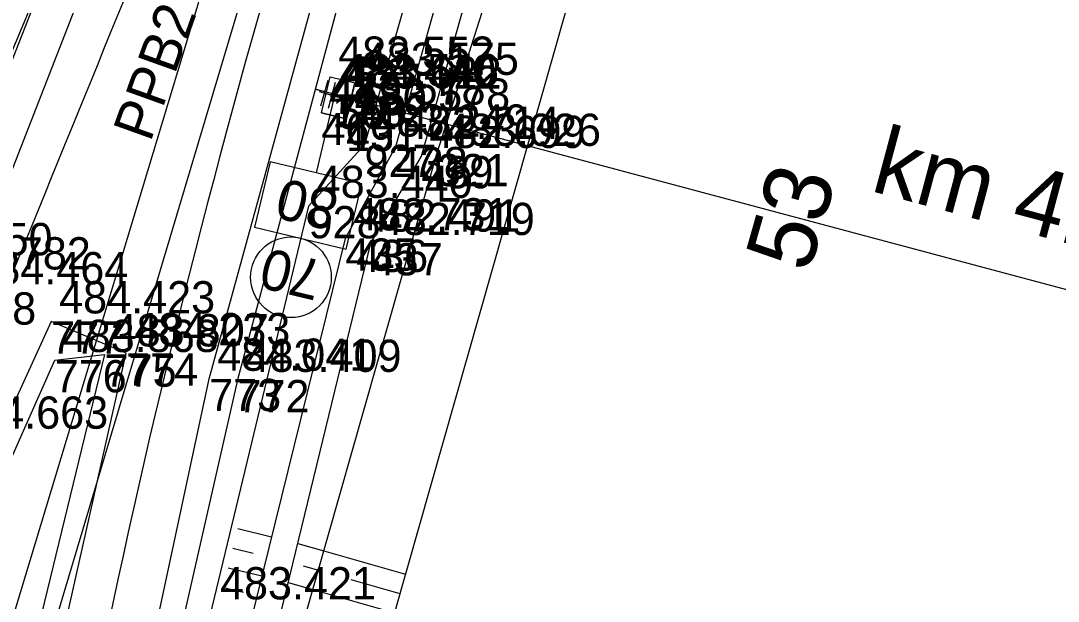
# Model space of a CAD drawing. Extents: x -874038 to -859694, y -1059487 to -1049069.
# Drawn here: x -866876 to -866837.42, y -1050772.45 to -1050750.85 of the extents above; entities that cross this region are included whole.
import ezdxf

# ---------------------------------------------------------------- set-up
doc = ezdxf.new("R2010")
doc.units = 0
for name, color, linetype in [('Vrstva 1', 7, 'Continuous'), ('Vrstva 11', 7, 'Continuous'), ('Vrstva 12', 7, 'Continuous'), ('Vrstva 13', 7, 'Continuous'), ('Vrstva 23', 7, 'Continuous'), ('Vrstva 3', 7, 'Continuous'), ('Vrstva 4', 7, 'Continuous'), ('Vrstva 44', 7, 'Continuous'), ('Vrstva 48', 7, 'Continuous'), ('Vrstva 49', 7, 'Continuous'), ('Vrstva 5', 7, 'Continuous'), ('Vrstva 6', 7, 'Continuous'), ('Vrstva 60', 7, 'Continuous'), ('Vrstva 61', 7, 'Continuous'), ('Vrstva 63', 7, 'Continuous'), ('Vrstva 7', 7, 'Continuous')]:
    doc.layers.add(name, color=color, linetype=linetype)

msp = doc.modelspace()

# ---------------------------------------------------------------- linework, layer by layer
at = {"layer": 'Vrstva 1'}
msp.add_arc((-866539.48, -1050843.456), 340.562, 163.73547, 173.43306, dxfattribs=at)
msp.add_spline([(-866866.581, -1050736.738), (-866870.906, -1050747.039), (-866878.845, -1050766.33), (-866887.686, -1050786.453)], degree=3, dxfattribs=at)
at = {"layer": 'Vrstva 11'}
for p, q in [((-866864.834, -1050754.023), (-866864.561, -1050753.06)), ((-866864.697, -1050753.542), (-866863.735, -1050753.814)), ((-866863.871, -1050754.296), (-866863.598, -1050753.333))]:
    msp.add_line(p, q, dxfattribs=at)
at = {"layer": 'Vrstva 12'}
for points in [[(-866864.816, -1050754.28), (-866864.492, -1050752.94), (-866863.577, -1050753.167), (-866863.9, -1050754.502), (-866864.816, -1050754.28)], [(-866864.492, -1050752.94), (-866863.577, -1050753.167)], [(-866863.9, -1050754.502), (-866863.9, -1050754.502), (-866863.577, -1050753.167), (-866863.577, -1050753.167)], [(-866864.816, -1050754.28), (-866863.9, -1050754.502)]]:
    msp.add_lwpolyline(points, dxfattribs=at)
at = {"layer": 'Vrstva 13'}
for p, q in [((-866859.113, -1050745.02), (-866862.056, -1050755.548)), ((-866862.056, -1050755.548), (-866863.928, -1050758.953)), ((-866863.928, -1050758.953), (-866870.485, -1050785.449))]:
    msp.add_line(p, q, dxfattribs=at)
msp.add_lwpolyline([(-866869.435, -1050785.682), (-866862.985, -1050759.125), (-866861.101, -1050755.887), (-866858.093, -1050745.283), (-866857.657, -1050739.624), (-866853.141, -1050726.153)], dxfattribs=at)
at = {"layer": 'Vrstva 23'}
msp.add_lwpolyline([(-866860.091, -1050744.519), (-866863.217, -1050755.466), (-866865.293, -1050757.745), (-866868.888, -1050772.679), (-866871.977, -1050788.759), (-866873.748, -1050800.936), (-866875.048, -1050813.205), (-866876.041, -1050829.553), (-866876.177, -1050845.923), (-866875.472, -1050862.297), (-866873.902, -1050878.655), (-866871.491, -1050894.865), (-866868.278, -1050910.955), (-866864.193, -1050926.852), (-866859.318, -1050942.487)], dxfattribs=at)
at = {"layer": 'Vrstva 4'}
for p, q in [((-866868.991, -1050764.175), (-866863.095, -1050742.706)), ((-866862.275, -1050743.026), (-866867.938, -1050764.216)), ((-866874.869, -1050762.04), (-866892.274, -1050800.212)), ((-866872.076, -1050763.224), (-866874.869, -1050762.04)), ((-866872.878, -1050763.268), (-866876.724, -1050779.104)), ((-866875.741, -1050779.509), (-866872.076, -1050763.224)), ((-866874.734, -1050763.477), (-866872.878, -1050763.268)), ((-866891.238, -1050800.767), (-866874.734, -1050763.477)), ((-866872.377, -1050779.959), (-866868.991, -1050764.175)), ((-866867.938, -1050764.216), (-866871.451, -1050779.65))]:
    msp.add_line(p, q, dxfattribs=at)
for points in [[(-866878.099, -1050760.956), (-866869.769, -1050739.599), (-866865.751, -1050728.95), (-866863.436, -1050724.369)], [(-866892.733, -1050790.985), (-866891.263, -1050788.067), (-866879.491, -1050760.405), (-866874.327, -1050747.254)]]:
    msp.add_lwpolyline(points, dxfattribs=at)
at = {"layer": 'Vrstva 44'}
for points in [[(-866912.752, -1050826.723), (-866890.904, -1050786.8), (-866874.15, -1050746.784), (-866858.678, -1050710.211), (-866845.122, -1050668.894)], [(-866881.51, -1050790.314), (-866868.997, -1050748.913), (-866874.15, -1050746.784)]]:
    msp.add_lwpolyline(points, dxfattribs=at)
at = {"layer": 'Vrstva 48'}
for p, q in [((-866866.676, -1050770.059), (-866867.928, -1050769.758)), ((-866867.355, -1050770.668), (-866868.104, -1050770.487)), ((-866865.698, -1050770.295), (-866864.726, -1050770.572)), ((-866864.726, -1050770.572), (-866861.691, -1050771.435)), ((-866867.037, -1050771.516), (-866868.279, -1050771.216)), ((-866865.497, -1050771.132), (-866864.931, -1050771.293)), ((-866866.052, -1050771.753), (-866865.136, -1050772.014)), ((-866863.717, -1050771.638), (-866861.896, -1050772.156)), ((-866867.712, -1050772.124), (-866868.455, -1050771.946)), ((-866865.136, -1050772.015), (-866862.101, -1050772.877))]:
    msp.add_line(p, q, dxfattribs=at)
at = {"layer": 'Vrstva 49'}
for points in [[(-866870.679, -1050875.747), (-866872.53, -1050852.558), (-866873.22, -1050828.055), (-866867.257, -1050779.466), (-866860.524, -1050755.809), (-866853.019, -1050732.306), (-866844.747, -1050709.076), (-866836.666, -1050685.758), (-866827.324, -1050663.004), (-866815.747, -1050641.544), (-866813.39, -1050638.57)], [(-866813.39, -1050638.57), (-866814.614, -1050641.108), (-866825.174, -1050662.382), (-866840.16, -1050699.594), (-866853.045, -1050741.012), (-866865.294, -1050784.112), (-866869.459, -1050806.077), (-866871.336, -1050827.203), (-866872.249, -1050850.439), (-866870.679, -1050875.747)]]:
    msp.add_lwpolyline(points, dxfattribs=at)
at = {"layer": 'Vrstva 5'}
msp.add_line((-866863.585, -1050753.766), (-866865.043, -1050753.414), dxfattribs=at)
msp.add_lwpolyline([(-866864.314, -1050753.59), (-866865.016, -1050756.507), (-866866.717, -1050756.097), (-866867.302, -1050758.528), (-866863.9, -1050759.347), (-866863.315, -1050756.916), (-866865.016, -1050756.507)], dxfattribs=at)
msp.add_circle((-866865.952, -1050760.396), 1.5, dxfattribs=at)
at = {"layer": 'Vrstva 6'}
msp.add_line((-866824.051, -1050764.35), (-866865.046, -1050753.394), dxfattribs=at)
at = {"layer": 'Vrstva 60'}
for p, q in [((-866864.492, -1050752.94), (-866864.492, -1050752.94)), ((-866863.577, -1050753.167), (-866863.577, -1050753.167)), ((-866863.577, -1050753.167), (-866863.577, -1050753.167)), ((-866864.421, -1050753.622), (-866864.421, -1050753.622)), ((-866864.314, -1050753.59), (-866864.314, -1050753.59)), ((-866864.216, -1050753.678), (-866864.216, -1050753.678)), ((-866864.816, -1050754.28), (-866864.816, -1050754.28)), ((-866863.9, -1050754.502), (-866863.9, -1050754.502)), ((-866863.9, -1050754.502), (-866863.9, -1050754.502)), ((-866863.217, -1050755.466), (-866863.217, -1050755.466)), ((-866862.056, -1050755.548), (-866862.056, -1050755.548)), ((-866861.101, -1050755.887), (-866861.101, -1050755.887)), ((-866860.524, -1050755.809), (-866860.524, -1050755.809)), ((-866865.293, -1050757.745), (-866865.293, -1050757.745)), ((-866863.928, -1050758.953), (-866863.928, -1050758.953)), ((-866863.526, -1050759), (-866863.526, -1050759)), ((-866862.985, -1050759.125), (-866862.985, -1050759.125)), ((-866874.869, -1050762.04), (-866874.869, -1050762.04)), ((-866872.878, -1050763.268), (-866872.878, -1050763.268)), ((-866872.076, -1050763.224), (-866872.076, -1050763.224)), ((-866874.734, -1050763.477), (-866874.734, -1050763.477)), ((-866868.991, -1050764.175), (-866868.991, -1050764.175)), ((-866867.938, -1050764.216), (-866867.938, -1050764.216))]:
    msp.add_line(p, q, dxfattribs=at)
at = {"layer": 'Vrstva 63'}
msp.add_line((-866878.429, -1050785.654), (-866847.948, -1050683.577), dxfattribs=at)
at = {"layer": 'Vrstva 7'}
for p, q in [((-866864.553, -1050754.104), (-866864.289, -1050753.14)), ((-866864.903, -1050753.49), (-866863.939, -1050753.754))]:
    msp.add_line(p, q, dxfattribs=at)

# ---------------------------------------------------------------- texts
at = {"layer": 'Vrstva 11'}
msp.add_text('53', height=2.5, rotation=74.1581, dxfattribs=at).set_placement((-866846.68, -1050760.278))
at = {"layer": 'Vrstva 3'}
msp.add_text('PPB2', height=1.5, rotation=70.2618, dxfattribs=at).set_placement((-866871.176, -1050755.399))
at = {"layer": 'Vrstva 5'}
for s, p in [('80', (-866864.092, -1050757.221)), ('70', (-866864.684, -1050759.815))]:
    msp.add_text(s, height=1.5, rotation=166.4665, dxfattribs=at).set_placement(p)
at = {"layer": 'Vrstva 6'}
msp.add_text('km 411,776', height=2.5, rotation=345.0373, dxfattribs=at).set_placement((-866844.455, -1050757.171))
at = {"layer": 'Vrstva 60'}
for s, p in [('47', (-866864.492, -1050754.14)), ('48', (-866863.577, -1050754.367)), ('130', (-866863.577, -1050754.367)), ('1482', (-866864.421, -1050754.822)), ('769', (-866864.314, -1050754.79)), ('50', (-866864.216, -1050754.878)), ('46', (-866864.816, -1050755.48)), ('49', (-866863.9, -1050755.702)), ('131', (-866863.9, -1050755.702)), ('927', (-866863.217, -1050756.666)), ('438', (-866862.056, -1050756.748)), ('439', (-866861.101, -1050757.087)), ('321', (-866860.524, -1050757.009)), ('928', (-866865.293, -1050758.945)), ('435', (-866863.928, -1050760.153)), ('436', (-866863.526, -1050760.2)), ('437', (-866862.985, -1050760.325)), ('778', (-866878.099, -1050762.156)), ('777', (-866874.869, -1050763.24)), ('775', (-866872.878, -1050764.468)), ('774', (-866872.076, -1050764.424)), ('776', (-866874.734, -1050764.677)), ('773', (-866868.991, -1050765.375)), ('772', (-866867.938, -1050765.416))]:
    msp.add_text(s, height=1.2, dxfattribs=at).set_placement(p)
at = {"layer": 'Vrstva 61'}
for s, p in [('483.552', (-866864.192, -1050752.64)), ('483.575', (-866863.277, -1050752.867)), ('483.175', (-866863.277, -1050752.867)), ('484.440', (-866864.121, -1050753.322)), ('483.546', (-866864.014, -1050753.29)), ('483.622', (-866863.916, -1050753.378)), ('483.578', (-866864.516, -1050753.98)), ('483.578', (-866863.6, -1050754.202)), ('483.178', (-866863.6, -1050754.202)), ('483.249', (-866862.917, -1050755.166)), ('482.714', (-866861.756, -1050755.248)), ('482.699', (-866860.801, -1050755.587)), ('483.026', (-866860.224, -1050755.509)), ('483.440', (-866864.993, -1050757.445)), ('482.731', (-866863.628, -1050758.653)), ('482.491', (-866863.226, -1050758.7)), ('482.719', (-866862.685, -1050758.825)), ('483.850', (-866880.612, -1050759.576)), ('483.782', (-866879.191, -1050760.105)), ('484.464', (-866877.799, -1050760.656)), ('484.423', (-866874.569, -1050761.74)), ('483.807', (-866872.578, -1050762.968)), ('484.233', (-866871.776, -1050762.924)), ('483.868', (-866874.434, -1050763.177)), ('484.041', (-866868.691, -1050763.875)), ('483.409', (-866867.638, -1050763.916)), ('484.663', (-866878.545, -1050766.03)), ('483.421', (-866868.588, -1050772.379))]:
    msp.add_text(s, height=1.2, dxfattribs=at).set_placement(p)

doc.saveas('drawing.dxf')
